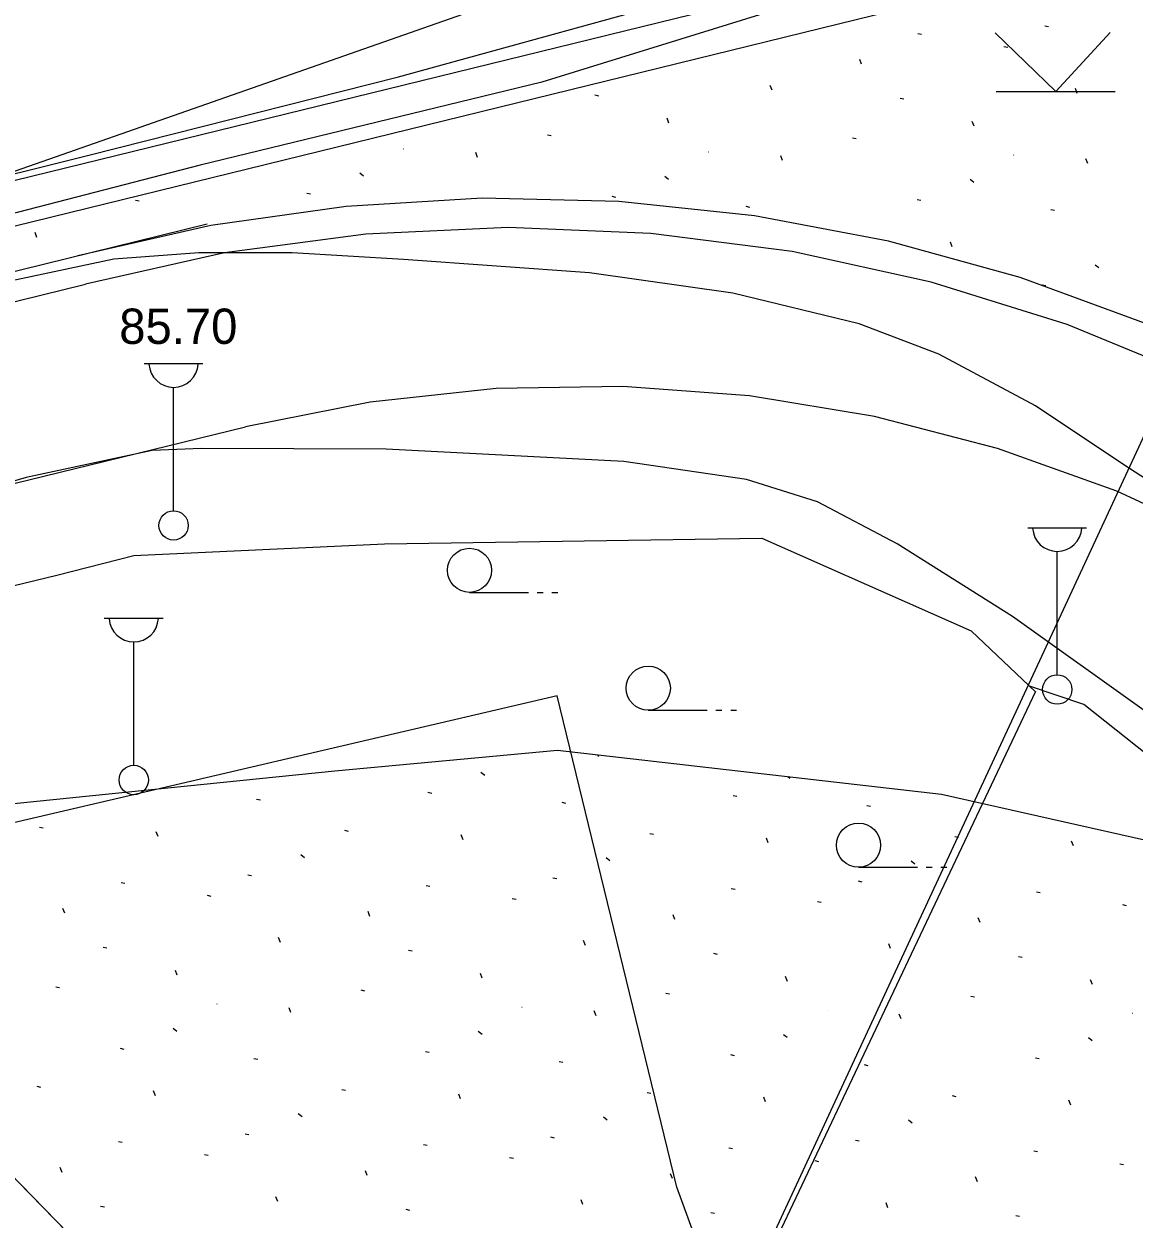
# Model space of a CAD drawing. Extents: x 412225 to 413380, y 4456471 to 4457189.
# Drawn here: x 412584.3 to 412622.02, y 4456681.66 to 4456722.27 of the extents above; entities that cross this region are included whole.
import ezdxf

# ---------------------------------------------------------------- set-up
doc = ezdxf.new("R2010")
doc.units = 0
for name, color, linetype in [('0_HALİHAZIR', 7, 'Continuous'), ('0_KADASTRO', 7, 'Continuous'), ('ADA_ONCEPHE', 7, 'Continuous'), ('KALDIRIM', 7, 'Continuous'), ('Level 41', 7, 'Continuous'), ('SINIR_FONKSIYON', 7, 'Continuous')]:
    doc.layers.add(name, color=color, linetype=linetype)

msp = doc.modelspace()

# ---------------------------------------------------------------- linework, layer by layer
at = {"layer": '0_HALİHAZIR'}
for p, q in [((412619.36, 4456719.976), (412617.301, 4456721.966)), ((412619.36, 4456719.976), (412621.211, 4456721.986)), ((412617.34, 4456719.976), (412621.381, 4456719.976)), ((412588.381, 4456710.731), (412590.381, 4456710.731)), ((412589.381, 4456705.731), (412589.381, 4456709.924)), ((412618.41, 4456705.155), (412620.41, 4456705.155)), ((412619.41, 4456700.155), (412619.41, 4456704.348)), ((412599.439, 4456702.956), (412601.439, 4456702.956)), ((412601.739, 4456702.956), (412601.939, 4456702.956)), ((412602.239, 4456702.956), (412602.439, 4456702.956)), ((412587.028, 4456702.082), (412589.028, 4456702.082)), ((412588.028, 4456697.082), (412588.028, 4456701.275)), ((412605.513, 4456698.953), (412607.513, 4456698.953)), ((412607.813, 4456698.953), (412608.013, 4456698.953)), ((412608.313, 4456698.953), (412608.513, 4456698.953)), ((412612.659, 4456693.617), (412614.659, 4456693.617)), ((412614.959, 4456693.617), (412615.159, 4456693.617)), ((412615.459, 4456693.617), (412615.659, 4456693.617))]:
    msp.add_line(p, q, dxfattribs=at)
for points in [[(412626.741, 4456729.666), (412623.854, 4456728.127), (412619.707, 4456726.226), (412612.923, 4456723.71), (412601.894, 4456720.294), (412590.282, 4456717.478), (412577.576, 4456714.185), (412558.626, 4456709.601), (412538.989, 4456704.81), (412512.784, 4456698.443), (412490.003, 4456692.816), (412471.784, 4456688.802)], [(412520.389, 4456701.919), (412536.769, 4456705.758), (412550.738, 4456709.25), (412563.272, 4456711.982), (412576.951, 4456715.432), (412586.498, 4456717.808), (412597.028, 4456720.477), (412605.672, 4456722.855)], [(412625.507, 4456704.807), (412621.641, 4456707.314), (412618.67, 4456709.292), (412615.389, 4456711.052), (412612.679, 4456712.081), (412608.39, 4456713.119), (412603.514, 4456713.82), (412597.196, 4456714.27), (412593.413, 4456714.494), (412590.24, 4456714.497), (412587.351, 4456714.274), (412583.828, 4456713.532), (412575.723, 4456711.408), (412560.345, 4456707.55), (412543.872, 4456703.315), (412520.303, 4456697.644)], [(412622.607, 4456698.771), (412617.89, 4456702.137), (412613.975, 4456704.611), (412611.258, 4456706.034), (412608.848, 4456706.788), (412604.68, 4456707.401), (412596.604, 4456707.825), (412590.325, 4456707.848), (412588.649, 4456707.774), (412584.373, 4456706.857), (412568.53, 4456702.236), (412562.443, 4456700.322), (412558.684, 4456698.919), (412557.916, 4456698.563), (412557.463, 4456698.112), (412557.419, 4456697.75), (412557.597, 4456696.832), (412558.277, 4456693.045), (412558.238, 4456692.305), (412557.738, 4456691.64), (412539.644, 4456686.97), (412534.256, 4456685.659)], [(412557.634, 4456696.626), (412571.602, 4456700.2), (412585.409, 4456703.542), (412588.029, 4456704.205), (412596.553, 4456704.609), (412609.371, 4456704.797), (412616.485, 4456701.647), (412618.67, 4456699.58)], [(412645.677, 4456641.033), (412646.088, 4456646.595), (412646.22, 4456653.27), (412646.134, 4456656.901), (412645.605, 4456660.493), (412643.891, 4456667.552), (412642.576, 4456672.02), (412639.714, 4456677.797), (412636.029, 4456683.61), (412631.941, 4456688.876), (412628.558, 4456692.031), (412623.943, 4456696.27), (412620.318, 4456699.143), (412618.47, 4456699.77)], [(412608.632, 4456678.359), (412607.679, 4456679.463), (412606.48, 4456682.749), (412602.422, 4456699.438), (412583.206, 4456694.95)], [(412610.816, 4456666.311), (412605.015, 4456670.713), (412618.678, 4456699.595)]]:
    msp.add_lwpolyline(points, dxfattribs=at)
for centre, radius in [((412589.381, 4456705.231), 0.5), ((412599.439, 4456703.706), 0.75), ((412605.513, 4456699.703), 0.75), ((412619.41, 4456699.655), 0.5), ((412588.028, 4456696.582), 0.5), ((412612.659, 4456694.367), 0.75)]:
    msp.add_circle(centre, radius, dxfattribs=at)
for centre in [(412589.381, 4456710.76), (412619.41, 4456705.185), (412588.028, 4456702.111)]:
    msp.add_arc(centre, 0.837, 183.298, 356.9072, dxfattribs=at)
at = {"layer": '0_KADASTRO'}
for points in [[(412511.64, 4456802.61), (412523.869, 4456823.705), (412617.056, 4456728.859), (412543.593, 4456703.12), (412527.466, 4456778.138), (412524.42, 4456784.89), (412522.24, 4456788.56), (412519.52, 4456792.85), (412512.99, 4456801.24)], [(412606.676, 4456674.478), (412627.37, 4456719.07), (412670.32, 4456675.65), (412657.308, 4456641.846)]]:
    msp.add_lwpolyline(points, close=True, dxfattribs=at)
msp.add_lwpolyline([(412522.032, 4456682.067), (412533.875, 4456684.989), (412566.743, 4456694.033), (412571.437, 4456693.236), (412576.186, 4456691.048), (412586.592, 4456680.371), (412605.918, 4456660.532), (412647.993, 4456626.953), (412648.984, 4456623.072), (412646.733, 4456616.993), (412609.99, 4456537.62), (412590.921, 4456495.2), (412588.019, 4456497.15), (412577.892, 4456503.673), (412577.288, 4456508.38), (412575.344, 4456509.9), (412570.449, 4456508.608), (412539.518, 4456529.233), (412506.276, 4456520.924)], dxfattribs=at)
at = {"layer": 'ADA_ONCEPHE'}
for p, q in [((412594.857, 4456696.898), (412602.425, 4456697.6)), ((412602.425, 4456697.6), (412615.48, 4456696.096)), ((412566.74, 4456694.03), (412594.857, 4456696.898)), ((412615.48, 4456696.096), (412624.749, 4456694.011))]:
    msp.add_line(p, q, dxfattribs=at)
at = {"layer": 'KALDIRIM'}
for p, q in [((412550.146, 4456708.658), (412621.462, 4456726.153)), ((412554.378, 4456708.152), (412621.819, 4456724.696)), ((412558.65, 4456707.656), (412590.523, 4456715.474)), ((412558.367, 4456706.556), (412586.39, 4456713.431)), ((412282.919, 4456632.809), (412591.829, 4456708.587))]:
    msp.add_line(p, q, dxfattribs=at)
for points in [[(412644.634, 4456695.649), (412641.55, 4456699.112), (412638.192, 4456702.311), (412634.584, 4456705.224), (412630.749, 4456707.832), (412626.713, 4456710.117), (412622.504, 4456712.063), (412618.149, 4456713.658), (412613.678, 4456714.891), (412609.121, 4456715.754), (412604.509, 4456716.24), (412599.873, 4456716.347), (412595.243, 4456716.074), (412590.652, 4456715.422), (412586.129, 4456714.396)], [(412646.303, 4456691.804), (412643.343, 4456695.638), (412640.06, 4456699.199), (412636.479, 4456702.461), (412632.628, 4456705.398), (412628.536, 4456707.989), (412624.233, 4456710.214), (412619.753, 4456712.056), (412615.13, 4456713.5), (412610.399, 4456714.536), (412605.595, 4456715.156), (412600.756, 4456715.356), (412595.917, 4456715.133), (412591.116, 4456714.49), (412586.39, 4456713.431)], [(412651.129, 4456658.366), (412651.259, 4456662.674), (412651.002, 4456666.977), (412650.361, 4456671.24), (412649.339, 4456675.428), (412647.946, 4456679.507), (412646.192, 4456683.444), (412644.093, 4456687.209), (412641.664, 4456690.77), (412638.925, 4456694.099), (412635.899, 4456697.168), (412632.609, 4456699.954), (412629.083, 4456702.434), (412625.349, 4456704.587), (412621.437, 4456706.396), (412617.378, 4456707.847), (412613.205, 4456708.928), (412608.952, 4456709.631), (412604.653, 4456709.949), (412600.343, 4456709.88), (412596.057, 4456709.425), (412591.829, 4456708.587)]]:
    msp.add_lwpolyline(points, dxfattribs=at)
at = {"layer": 'Level 41'}
for p, q in [((412618.984, 4456722.21), (412619.11, 4456722.185)), ((412618.984, 4456722.21), (412619.11, 4456722.185)), ((412614.676, 4456721.95), (412614.802, 4456721.925)), ((412614.676, 4456721.95), (412614.802, 4456721.925)), ((412617.601, 4456721.51), (412617.727, 4456721.484)), ((412617.601, 4456721.51), (412617.727, 4456721.484)), ((412612.762, 4456720.9), (412612.698, 4456721.063)), ((412612.762, 4456720.9), (412612.698, 4456721.063)), ((412609.721, 4456720.017), (412609.658, 4456720.181)), ((412609.721, 4456720.017), (412609.658, 4456720.181)), ((412620.089, 4456719.911), (412620.026, 4456720.075)), ((412620.089, 4456719.911), (412620.026, 4456720.075)), ((412603.702, 4456719.858), (412603.828, 4456719.833)), ((412603.702, 4456719.858), (412603.828, 4456719.833)), ((412614.069, 4456719.752), (412614.195, 4456719.727)), ((412614.069, 4456719.752), (412614.195, 4456719.727)), ((412606.214, 4456718.903), (412606.152, 4456719.065)), ((412606.214, 4456718.903), (412606.152, 4456719.065)), ((412616.582, 4456718.797), (412616.519, 4456718.959)), ((412616.582, 4456718.797), (412616.519, 4456718.959)), ((412602.084, 4456718.507), (412602.21, 4456718.481)), ((412602.084, 4456718.507), (412602.21, 4456718.481)), ((412612.451, 4456718.401), (412612.577, 4456718.375)), ((412612.451, 4456718.401), (412612.577, 4456718.375)), ((412597.195, 4456718.032), (412597.203, 4456718.03)), ((412597.195, 4456718.032), (412597.203, 4456718.03)), ((412599.711, 4456717.737), (412599.648, 4456717.899)), ((412599.711, 4456717.737), (412599.648, 4456717.899)), ((412607.562, 4456717.926), (412607.571, 4456717.924)), ((412607.562, 4456717.926), (412607.571, 4456717.924)), ((412610.079, 4456717.63), (412610.016, 4456717.793)), ((412610.079, 4456717.63), (412610.016, 4456717.793)), ((412617.929, 4456717.82), (412617.938, 4456717.818)), ((412617.929, 4456717.82), (412617.938, 4456717.818)), ((412620.446, 4456717.524), (412620.383, 4456717.687)), ((412620.446, 4456717.524), (412620.383, 4456717.687)), ((412595.711, 4456717.208), (412595.837, 4456717.108)), ((412595.711, 4456717.208), (412595.837, 4456717.108)), ((412606.079, 4456717.102), (412606.205, 4456717.002)), ((412606.079, 4456717.102), (412606.205, 4456717.002)), ((412616.446, 4456716.996), (412616.572, 4456716.896)), ((412616.446, 4456716.996), (412616.572, 4456716.896)), ((412593.91, 4456716.522), (412594.036, 4456716.496)), ((412593.91, 4456716.522), (412594.036, 4456716.496)), ((412604.278, 4456716.416), (412604.404, 4456716.39)), ((412604.278, 4456716.416), (412604.404, 4456716.39)), ((412588.088, 4456716.287), (412588.214, 4456716.263)), ((412588.088, 4456716.287), (412588.214, 4456716.263)), ((412608.823, 4456716.075), (412608.949, 4456716.05)), ((412608.823, 4456716.075), (412608.949, 4456716.05)), ((412614.645, 4456716.31), (412614.771, 4456716.284)), ((412614.645, 4456716.31), (412614.771, 4456716.284)), ((412619.19, 4456715.969), (412619.316, 4456715.944)), ((412619.19, 4456715.969), (412619.316, 4456715.944)), ((412584.74, 4456715.018), (412584.676, 4456715.181)), ((412584.74, 4456715.018), (412584.676, 4456715.181)), ((412615.842, 4456714.7), (412615.779, 4456714.862)), ((412615.842, 4456714.7), (412615.779, 4456714.862)), ((412620.695, 4456714.091), (412620.822, 4456713.991)), ((412620.695, 4456714.091), (412620.822, 4456713.991)), ((412618.894, 4456713.404), (412619.02, 4456713.379)), ((412618.894, 4456713.404), (412619.02, 4456713.379)), ((412603.828, 4456697.377), (412603.803, 4456697.441)), ((412603.828, 4456697.377), (412603.803, 4456697.441)), ((412599.828, 4456696.849), (412599.954, 4456696.749)), ((412599.828, 4456696.849), (412599.954, 4456696.749)), ((412610.251, 4456696.698), (412610.321, 4456696.643)), ((412610.251, 4456696.698), (412610.321, 4456696.643)), ((412598.027, 4456696.162), (412598.153, 4456696.137)), ((412598.027, 4456696.162), (412598.153, 4456696.137)), ((412608.394, 4456696.056), (412608.52, 4456696.031)), ((412608.394, 4456696.056), (412608.52, 4456696.031)), ((412592.204, 4456695.928), (412592.33, 4456695.903)), ((412592.204, 4456695.928), (412592.33, 4456695.903)), ((412602.572, 4456695.822), (412602.698, 4456695.797)), ((412602.572, 4456695.822), (412602.698, 4456695.797)), ((412612.939, 4456695.716), (412613.065, 4456695.691)), ((412612.939, 4456695.716), (412613.065, 4456695.691)), ((412584.826, 4456694.979), (412584.951, 4456694.953)), ((412584.826, 4456694.979), (412584.951, 4456694.953)), ((412588.856, 4456694.658), (412588.793, 4456694.821)), ((412588.856, 4456694.658), (412588.793, 4456694.821)), ((412595.193, 4456694.873), (412595.318, 4456694.847)), ((412595.193, 4456694.873), (412595.318, 4456694.847)), ((412599.224, 4456694.552), (412599.16, 4456694.715)), ((412599.224, 4456694.552), (412599.16, 4456694.715)), ((412605.561, 4456694.767), (412605.686, 4456694.741)), ((412605.561, 4456694.767), (412605.686, 4456694.741)), ((412609.591, 4456694.446), (412609.528, 4456694.609)), ((412609.591, 4456694.446), (412609.528, 4456694.609)), ((412615.928, 4456694.661), (412616.053, 4456694.635)), ((412615.928, 4456694.661), (412616.053, 4456694.635)), ((412619.959, 4456694.34), (412619.895, 4456694.503)), ((412619.959, 4456694.34), (412619.895, 4456694.503)), ((412593.71, 4456694.05), (412593.836, 4456693.949)), ((412593.71, 4456694.05), (412593.836, 4456693.949)), ((412604.077, 4456693.944), (412604.203, 4456693.843)), ((412604.077, 4456693.944), (412604.203, 4456693.843)), ((412614.445, 4456693.838), (412614.571, 4456693.737)), ((412614.445, 4456693.838), (412614.571, 4456693.737)), ((412591.908, 4456693.363), (412592.034, 4456693.338)), ((412591.908, 4456693.363), (412592.034, 4456693.338)), ((412602.275, 4456693.257), (412602.401, 4456693.232)), ((412602.275, 4456693.257), (412602.401, 4456693.232)), ((412587.6, 4456693.103), (412587.726, 4456693.078)), ((412587.6, 4456693.103), (412587.726, 4456693.078)), ((412597.968, 4456692.997), (412598.094, 4456692.972)), ((412597.968, 4456692.997), (412598.094, 4456692.972)), ((412608.335, 4456692.891), (412608.461, 4456692.866)), ((412608.335, 4456692.891), (412608.461, 4456692.866)), ((412612.643, 4456693.151), (412612.769, 4456693.126)), ((412612.643, 4456693.151), (412612.769, 4456693.126)), ((412618.702, 4456692.785), (412618.828, 4456692.76)), ((412618.702, 4456692.785), (412618.828, 4456692.76)), ((412590.525, 4456692.663), (412590.651, 4456692.638)), ((412590.525, 4456692.663), (412590.651, 4456692.638)), ((412600.892, 4456692.557), (412601.018, 4456692.532)), ((412600.892, 4456692.557), (412601.018, 4456692.532)), ((412611.26, 4456692.451), (412611.386, 4456692.425)), ((412611.26, 4456692.451), (412611.386, 4456692.425)), ((412585.686, 4456692.054), (412585.622, 4456692.217)), ((412585.686, 4456692.054), (412585.622, 4456692.217)), ((412596.053, 4456691.948), (412595.989, 4456692.11)), ((412596.053, 4456691.948), (412595.989, 4456692.11)), ((412606.421, 4456691.841), (412606.357, 4456692.004)), ((412606.421, 4456691.841), (412606.357, 4456692.004)), ((412621.627, 4456692.345), (412621.753, 4456692.319)), ((412621.627, 4456692.345), (412621.753, 4456692.319)), ((412616.788, 4456691.735), (412616.724, 4456691.898)), ((412616.788, 4456691.735), (412616.724, 4456691.898)), ((412593.013, 4456691.064), (412592.95, 4456691.228)), ((412593.013, 4456691.064), (412592.95, 4456691.228)), ((412586.993, 4456690.905), (412587.119, 4456690.88)), ((412586.993, 4456690.905), (412587.119, 4456690.88)), ((412597.36, 4456690.799), (412597.487, 4456690.774)), ((412597.36, 4456690.799), (412597.487, 4456690.774)), ((412603.38, 4456690.958), (412603.317, 4456691.122)), ((412603.38, 4456690.958), (412603.317, 4456691.122)), ((412613.748, 4456690.852), (412613.685, 4456691.016)), ((412613.748, 4456690.852), (412613.685, 4456691.016)), ((412607.728, 4456690.693), (412607.854, 4456690.668)), ((412607.728, 4456690.693), (412607.854, 4456690.668)), ((412618.095, 4456690.587), (412618.221, 4456690.562)), ((412618.095, 4456690.587), (412618.221, 4456690.562)), ((412589.506, 4456689.951), (412589.443, 4456690.112)), ((412589.506, 4456689.951), (412589.443, 4456690.112)), ((412599.873, 4456689.844), (412599.811, 4456690.006)), ((412599.873, 4456689.844), (412599.811, 4456690.006)), ((412585.375, 4456689.554), (412585.502, 4456689.528)), ((412585.375, 4456689.554), (412585.502, 4456689.528)), ((412610.241, 4456689.738), (412610.178, 4456689.9)), ((412610.241, 4456689.738), (412610.178, 4456689.9)), ((412620.608, 4456689.632), (412620.546, 4456689.794)), ((412620.608, 4456689.632), (412620.546, 4456689.794)), ((412595.743, 4456689.448), (412595.869, 4456689.422)), ((412595.743, 4456689.448), (412595.869, 4456689.422)), ((412606.11, 4456689.342), (412606.236, 4456689.316)), ((412606.11, 4456689.342), (412606.236, 4456689.316)), ((412616.478, 4456689.236), (412616.604, 4456689.21)), ((412616.478, 4456689.236), (412616.604, 4456689.21)), ((412590.854, 4456688.973), (412590.862, 4456688.971)), ((412590.854, 4456688.973), (412590.862, 4456688.971)), ((412593.37, 4456688.678), (412593.307, 4456688.841)), ((412593.37, 4456688.678), (412593.307, 4456688.841)), ((412601.221, 4456688.867), (412601.23, 4456688.865)), ((412601.221, 4456688.867), (412601.23, 4456688.865)), ((412603.738, 4456688.572), (412603.674, 4456688.734)), ((412603.738, 4456688.572), (412603.674, 4456688.734)), ((412611.588, 4456688.761), (412611.597, 4456688.759)), ((412611.588, 4456688.761), (412611.597, 4456688.759)), ((412614.105, 4456688.465), (412614.042, 4456688.628)), ((412614.105, 4456688.465), (412614.042, 4456688.628)), ((412621.956, 4456688.655), (412621.965, 4456688.653)), ((412621.956, 4456688.655), (412621.965, 4456688.653)), ((412589.37, 4456688.149), (412589.496, 4456688.05)), ((412589.37, 4456688.149), (412589.496, 4456688.05)), ((412599.737, 4456688.043), (412599.864, 4456687.943)), ((412599.737, 4456688.043), (412599.864, 4456687.943)), ((412610.105, 4456687.937), (412610.231, 4456687.837)), ((412610.105, 4456687.937), (412610.231, 4456687.837)), ((412620.472, 4456687.831), (412620.599, 4456687.731)), ((412620.472, 4456687.831), (412620.599, 4456687.731)), ((412587.569, 4456687.463), (412587.695, 4456687.437)), ((412587.569, 4456687.463), (412587.695, 4456687.437)), ((412592.114, 4456687.122), (412592.24, 4456687.098)), ((412592.114, 4456687.122), (412592.24, 4456687.098)), ((412597.937, 4456687.357), (412598.063, 4456687.331)), ((412597.937, 4456687.357), (412598.063, 4456687.331)), ((412608.304, 4456687.251), (412608.43, 4456687.225)), ((412608.304, 4456687.251), (412608.43, 4456687.225)), ((412618.672, 4456687.145), (412618.798, 4456687.119)), ((412618.672, 4456687.145), (412618.798, 4456687.119)), ((412602.482, 4456687.016), (412602.608, 4456686.991)), ((412602.482, 4456687.016), (412602.608, 4456686.991)), ((412612.849, 4456686.91), (412612.975, 4456686.885)), ((412612.849, 4456686.91), (412612.975, 4456686.885)), ((412584.736, 4456686.174), (412584.861, 4456686.148)), ((412584.736, 4456686.174), (412584.861, 4456686.148)), ((412588.766, 4456685.853), (412588.703, 4456686.016)), ((412588.766, 4456685.853), (412588.703, 4456686.016)), ((412595.103, 4456686.067), (412595.228, 4456686.042)), ((412595.103, 4456686.067), (412595.228, 4456686.042)), ((412599.134, 4456685.747), (412599.07, 4456685.91)), ((412599.134, 4456685.747), (412599.07, 4456685.91)), ((412605.47, 4456685.961), (412605.595, 4456685.936)), ((412605.47, 4456685.961), (412605.595, 4456685.936)), ((412609.501, 4456685.641), (412609.438, 4456685.803)), ((412609.501, 4456685.641), (412609.438, 4456685.803)), ((412615.838, 4456685.855), (412615.963, 4456685.829)), ((412615.838, 4456685.855), (412615.963, 4456685.829)), ((412619.868, 4456685.534), (412619.805, 4456685.697)), ((412619.868, 4456685.534), (412619.805, 4456685.697)), ((412593.619, 4456685.245), (412593.746, 4456685.144)), ((412593.619, 4456685.245), (412593.746, 4456685.144)), ((412603.987, 4456685.139), (412604.113, 4456685.038)), ((412603.987, 4456685.139), (412604.113, 4456685.038)), ((412614.354, 4456685.033), (412614.481, 4456684.932)), ((412614.354, 4456685.033), (412614.481, 4456684.932)), ((412587.51, 4456684.298), (412587.636, 4456684.273)), ((412587.51, 4456684.298), (412587.636, 4456684.273)), ((412591.818, 4456684.557), (412591.944, 4456684.533)), ((412591.818, 4456684.557), (412591.944, 4456684.533)), ((412602.185, 4456684.451), (412602.311, 4456684.427)), ((412602.185, 4456684.451), (412602.311, 4456684.427)), ((412612.553, 4456684.345), (412612.679, 4456684.32)), ((412612.553, 4456684.345), (412612.679, 4456684.32)), ((412590.435, 4456683.858), (412590.561, 4456683.832)), ((412590.435, 4456683.858), (412590.561, 4456683.832)), ((412597.877, 4456684.191), (412598.003, 4456684.167)), ((412597.877, 4456684.191), (412598.003, 4456684.167)), ((412608.245, 4456684.085), (412608.371, 4456684.061)), ((412608.245, 4456684.085), (412608.371, 4456684.061)), ((412618.612, 4456683.979), (412618.738, 4456683.954)), ((412618.612, 4456683.979), (412618.738, 4456683.954)), ((412600.802, 4456683.752), (412600.928, 4456683.726)), ((412600.802, 4456683.752), (412600.928, 4456683.726)), ((412611.17, 4456683.646), (412611.296, 4456683.62)), ((412611.17, 4456683.646), (412611.296, 4456683.62)), ((412621.537, 4456683.54), (412621.663, 4456683.514)), ((412621.537, 4456683.54), (412621.663, 4456683.514)), ((412585.596, 4456683.248), (412585.532, 4456683.411)), ((412585.596, 4456683.248), (412585.532, 4456683.411)), ((412595.963, 4456683.142), (412595.899, 4456683.305)), ((412595.963, 4456683.142), (412595.899, 4456683.305)), ((412606.331, 4456683.036), (412606.266, 4456683.199)), ((412606.331, 4456683.036), (412606.266, 4456683.199)), ((412616.698, 4456682.93), (412616.634, 4456683.093)), ((412616.698, 4456682.93), (412616.634, 4456683.093)), ((412592.923, 4456682.258), (412592.86, 4456682.422)), ((412592.923, 4456682.258), (412592.86, 4456682.422)), ((412603.29, 4456682.152), (412603.227, 4456682.316)), ((412603.29, 4456682.152), (412603.227, 4456682.316)), ((412586.903, 4456682.099), (412587.029, 4456682.075)), ((412586.903, 4456682.099), (412587.029, 4456682.075)), ((412597.27, 4456681.993), (412597.396, 4456681.969)), ((412597.27, 4456681.993), (412597.396, 4456681.969)), ((412607.638, 4456681.887), (412607.764, 4456681.862)), ((412607.638, 4456681.887), (412607.764, 4456681.862)), ((412613.658, 4456682.046), (412613.594, 4456682.21)), ((412613.658, 4456682.046), (412613.594, 4456682.21)), ((412618.005, 4456681.781), (412618.131, 4456681.756)), ((412618.005, 4456681.781), (412618.131, 4456681.756))]:
    msp.add_line(p, q, dxfattribs=at)
at = {"layer": 'SINIR_FONKSIYON'}
msp.add_lwpolyline([(412566.74, 4456694.03), (412568.244, 4456693.777), (412571.44, 4456693.24), (412576.19, 4456691.05), (412586.59, 4456680.37), (412605.92, 4456660.53), (412645.074, 4456629.278)], dxfattribs=at)

# ---------------------------------------------------------------- texts
at = {"layer": '0_HALİHAZIR'}
msp.add_text('85.70', height=1.2, dxfattribs=at).set_placement((412587.535, 4456711.399))

doc.saveas('drawing.dxf')
